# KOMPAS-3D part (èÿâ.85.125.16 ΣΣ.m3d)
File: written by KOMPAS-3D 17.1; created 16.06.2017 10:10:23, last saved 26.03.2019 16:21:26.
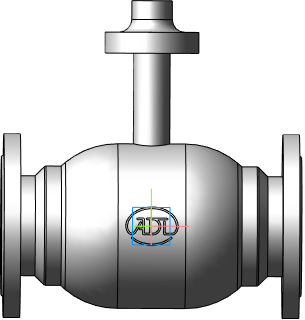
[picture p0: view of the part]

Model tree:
1. Операция без истории:2  (labels: Сталь 20  ГОСТ 1050-88)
